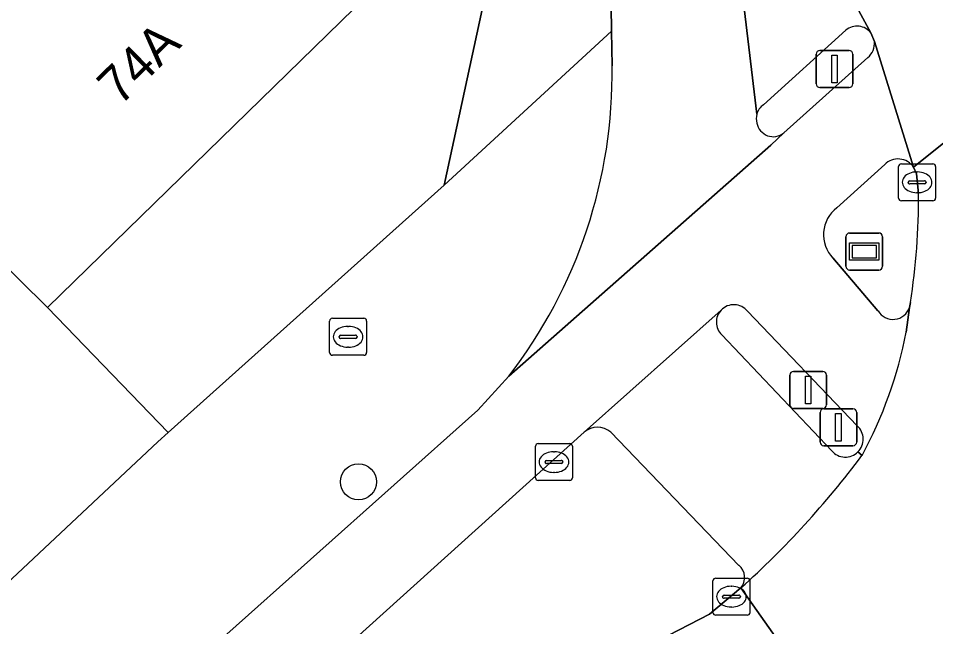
# Model space of a CAD drawing. Extents: x 161881 to 162523, y 381678 to 382381.
# Drawn here: x 162473.96 to 162498.77, y 381812.72 to 381829.16 of the extents above; entities that cross this region are included whole.
import ezdxf

# ---------------------------------------------------------------- set-up
doc = ezdxf.new("R2010")
doc.units = 0
for name, color, linetype in [('IMGEO_Boom', 7, 'Continuous'), ('IMGEO_Brandkraan', 7, 'Continuous'), ('IMGEO_Erf', 7, 'Continuous'), ('IMGEO_Fietspad_gesloten', 7, 'Continuous'), ('IMGEO_Kolk', 7, 'Continuous'), ('IMGEO_Pand', 7, 'Continuous'), ('IMGEO_Pand_nummerreeks', 7, 'Continuous'), ('IMGEO_Rijbaan_lokaal_gesloten', 7, 'Continuous'), ('IMGEO_Rijbaan_regionaal_gesloten', 7, 'Continuous'), ('IMGEO_Verkeerseiland_open', 7, 'Continuous'), ('IMGEO_Verkeersregelinstallatiepaal', 7, 'Continuous'), ('IMGEO_Voetpad_open', 7, 'Continuous'), ('IMGEO_Wegwijzer', 7, 'Continuous')]:
    doc.layers.add(name, color=color, linetype=linetype)

msp = doc.modelspace()

# ---------------------------------------------------------------- linework, layer by layer
at = {"layer": 'IMGEO_Boom'}
msp.add_circle((162483.161, 381816.631), 0.489, dxfattribs=at)
at = {"layer": 'IMGEO_Brandkraan'}
for p, q in [((162482.381, 381820.127), (162482.381, 381820.979)), ((162482.456, 381821.053), (162483.308, 381821.053)), ((162483.382, 381820.979), (162483.382, 381820.127)), ((162482.683, 381820.596), (162483.081, 381820.596)), ((162482.869, 381820.833), (162482.894, 381820.833)), ((162482.64, 381820.547), (162482.64, 381820.559)), ((162483.078, 381820.51), (162482.68, 381820.51)), ((162483.124, 381820.559), (162483.124, 381820.547)), ((162482.892, 381820.273), (162482.867, 381820.273)), ((162483.308, 381820.053), (162482.456, 381820.053))]:
    msp.add_line(p, q, dxfattribs=at)
for points in [[(162482.381, 381820.127), (162482.381, 381820.979)], [(162482.456, 381821.053), (162483.308, 381821.053)], [(162483.382, 381820.979), (162483.382, 381820.127)], [(162483.308, 381820.053), (162482.456, 381820.053)]]:
    msp.add_lwpolyline(points, dxfattribs=at)
for centre, radius, start, end in [((162482.458, 381820.977), 0.0765, 91.552, 178.448), ((162482.458, 381820.977), 0.0765, 91.552, 178.448), ((162483.306, 381820.977), 0.0765, 1.552, 88.448), ((162483.306, 381820.977), 0.0765, 1.552, 88.448), ((162482.68, 381820.556), 0.0403, 85.8775, 175.7526), ((162483.085, 381820.558), 0.0386, 1.7309, 96.639), ((162482.677, 381820.546), 0.0366, 178.938, 274.7102), ((162483.081, 381820.553), 0.043, 264.8664, 352.4533), ((162482.458, 381820.129), 0.0765, 181.552, 268.448), ((162482.458, 381820.129), 0.0765, 181.552, 268.448), ((162483.306, 381820.129), 0.0765, 271.552, 358.448), ((162483.306, 381820.129), 0.0765, 271.552, 358.448)]:
    msp.add_arc(centre, radius, start, end, dxfattribs=at)
for centre, major_axis, ratio, start_param, end_param in [((162482.868, 381820.553), (-0.387, 0.002), 0.722429, 4.712389, 7.853982), ((162482.893, 381820.553), (-0.39, 0.002), 0.717154, 1.570796, 4.712389)]:
    msp.add_ellipse(centre, major_axis=major_axis, ratio=ratio, start_param=start_param, end_param=end_param, dxfattribs=at)
at = {"layer": 'IMGEO_Erf'}
msp.add_lwpolyline([(162462.828, 381803.734), (162477.732, 381817.717), (162478.012, 381817.966), (162474.756, 381821.342), (162473.995, 381822.096), (162473.56, 381822.527)], dxfattribs=at)
at = {"layer": 'IMGEO_Fietspad_gesloten'}
for points in [[(162489.918, 381834.902), (162490.005, 381828.82), (162490.018, 381827.882)], [(162493.934, 381826.575), (162493.476, 381830.429)], [(162498.173, 381825.138), (162497.115, 381828.537)], [(162496.933, 381828.101), (162494.66, 381826.067), (162494.314, 381825.738), (162487.223, 381819.486), (162486.388, 381818.566), (162472.804, 381806.46), (162471.599, 381805.42)], [(162487.223, 381819.486), (162494.314, 381825.738), (162494.66, 381826.067)], [(162496.097, 381824.037), (162497.393, 381825.209)], [(162497.209, 381821.253), (162495.986, 381822.684)], [(162497.97, 381820.679), (162498.062, 381821.347)], [(162474.799, 381804.92), (162489.267, 381817.973), (162492.968, 381821.276)], [(162493.678, 381821.244), (162496.648, 381818.145)], [(162496.668, 381817.44), (162496.777, 381817.342)]]:
    msp.add_lwpolyline(points, dxfattribs=at)
for centre, radius, start, end in [((162496.594, 381828.498), 0.522, 310.4585, 4.2271), ((162476.678, 381827.66), 13.342, 322.2203, 0.9549), ((162494.357, 381826.457), 0.439, 164.4796, 196.4674), ((162494.376, 381826.411), 0.447, 190.0967, 309.5563), ((162497.754, 381824.859), 0.503, 33.6837, 135.9142), ((162496.641, 381823.311), 0.907, 126.8494, 223.7705), ((162493.309, 381820.949), 0.472, 38.6319, 136.2069), ((162497.614, 381821.498), 0.473, 211.2431, 341.3341), ((162486.621, 381822.855), 11.556, 331.5076, 349.1477), ((162496.328, 381817.783), 0.483, 314.6979, 48.552)]:
    msp.add_arc(centre, radius, start, end, dxfattribs=at)
at = {"layer": 'IMGEO_Kolk'}
for p, q in [((162497.767, 381824.304), (162497.767, 381825.156)), ((162497.842, 381825.23), (162498.694, 381825.23)), ((162498.768, 381825.156), (162498.768, 381824.304)), ((162498.255, 381825.01), (162498.28, 381825.01)), ((162498.026, 381824.724), (162498.026, 381824.736)), ((162498.464, 381824.687), (162498.066, 381824.687)), ((162498.069, 381824.773), (162498.467, 381824.773)), ((162498.51, 381824.736), (162498.51, 381824.724)), ((162498.278, 381824.45), (162498.253, 381824.45)), ((162498.694, 381824.23), (162497.842, 381824.23)), ((162488.022, 381817.667), (162488.874, 381817.667)), ((162487.947, 381816.741), (162487.947, 381817.593)), ((162488.435, 381817.447), (162488.46, 381817.447)), ((162488.948, 381817.593), (162488.948, 381816.741)), ((162488.206, 381817.161), (162488.206, 381817.173)), ((162488.644, 381817.124), (162488.246, 381817.124)), ((162488.249, 381817.21), (162488.647, 381817.21)), ((162488.69, 381817.173), (162488.69, 381817.161)), ((162488.458, 381816.887), (162488.433, 381816.887)), ((162488.874, 381816.667), (162488.022, 381816.667)), ((162492.747, 381813.101), (162492.747, 381813.953)), ((162492.822, 381814.027), (162493.674, 381814.027)), ((162493.748, 381813.953), (162493.748, 381813.101)), ((162493.235, 381813.807), (162493.26, 381813.807)), ((162493.006, 381813.521), (162493.006, 381813.533)), ((162493.444, 381813.484), (162493.046, 381813.484)), ((162493.049, 381813.57), (162493.447, 381813.57)), ((162493.49, 381813.533), (162493.49, 381813.521)), ((162493.258, 381813.247), (162493.233, 381813.247)), ((162493.674, 381813.027), (162492.822, 381813.027))]:
    msp.add_line(p, q, dxfattribs=at)
for points in [[(162497.767, 381824.304), (162497.767, 381825.156)], [(162497.842, 381825.23), (162498.694, 381825.23)], [(162498.768, 381825.156), (162498.768, 381824.304)], [(162498.694, 381824.23), (162497.842, 381824.23)], [(162488.022, 381817.667), (162488.874, 381817.667)], [(162487.947, 381816.741), (162487.947, 381817.593)], [(162488.948, 381817.593), (162488.948, 381816.741)], [(162488.874, 381816.667), (162488.022, 381816.667)], [(162492.747, 381813.101), (162492.747, 381813.953)], [(162492.822, 381814.027), (162493.674, 381814.027)], [(162493.748, 381813.953), (162493.748, 381813.101)], [(162493.674, 381813.027), (162492.822, 381813.027)]]:
    msp.add_lwpolyline(points, dxfattribs=at)
for centre, radius, start, end in [((162497.844, 381825.154), 0.0765, 91.552, 178.448), ((162497.844, 381825.154), 0.0765, 91.552, 178.448), ((162498.692, 381825.154), 0.0765, 1.552, 88.448), ((162498.692, 381825.154), 0.0765, 1.552, 88.448), ((162498.066, 381824.733), 0.0403, 85.8775, 175.7526), ((162498.063, 381824.723), 0.0366, 178.938, 274.7102), ((162498.467, 381824.73), 0.043, 264.8664, 352.4533), ((162498.471, 381824.735), 0.0386, 1.7309, 96.639), ((162497.844, 381824.306), 0.0765, 181.552, 268.448), ((162497.844, 381824.306), 0.0765, 181.552, 268.448), ((162498.692, 381824.306), 0.0765, 271.552, 358.448), ((162498.692, 381824.306), 0.0765, 271.552, 358.448), ((162488.024, 381817.591), 0.0765, 91.552, 178.448), ((162488.024, 381817.591), 0.0765, 91.552, 178.448), ((162488.872, 381817.591), 0.0765, 1.552, 88.448), ((162488.872, 381817.591), 0.0765, 1.552, 88.448), ((162488.246, 381817.17), 0.0403, 85.8775, 175.7526), ((162488.243, 381817.16), 0.0366, 178.938, 274.7102), ((162488.647, 381817.167), 0.043, 264.8664, 352.4533), ((162488.651, 381817.172), 0.0386, 1.7309, 96.639), ((162488.024, 381816.743), 0.0765, 181.552, 268.448), ((162488.024, 381816.743), 0.0765, 181.552, 268.448), ((162488.872, 381816.743), 0.0765, 271.552, 358.448), ((162488.872, 381816.743), 0.0765, 271.552, 358.448), ((162492.824, 381813.951), 0.0765, 91.552, 178.448), ((162492.824, 381813.951), 0.0765, 91.552, 178.448), ((162493.672, 381813.951), 0.0765, 1.552, 88.448), ((162493.672, 381813.951), 0.0765, 1.552, 88.448), ((162493.046, 381813.53), 0.0403, 85.8775, 175.7526), ((162493.043, 381813.52), 0.0366, 178.938, 274.7102), ((162493.447, 381813.527), 0.043, 264.8664, 352.4533), ((162493.451, 381813.532), 0.0386, 1.7309, 96.639), ((162492.824, 381813.103), 0.0765, 181.552, 268.448), ((162492.824, 381813.103), 0.0765, 181.552, 268.448), ((162493.672, 381813.103), 0.0765, 271.552, 358.448), ((162493.672, 381813.103), 0.0765, 271.552, 358.448)]:
    msp.add_arc(centre, radius, start, end, dxfattribs=at)
for centre, major_axis, ratio, start_param, end_param in [((162498.254, 381824.73), (-0.387, 0.002), 0.722429, 4.712389, 7.853982), ((162498.279, 381824.73), (-0.39, 0.002), 0.717154, 1.570796, 4.712389), ((162488.434, 381817.167), (-0.387, 0.002), 0.722429, 4.712389, 7.853982), ((162488.459, 381817.167), (-0.39, 0.002), 0.717154, 1.570796, 4.712389), ((162493.234, 381813.527), (-0.387, 0.002), 0.722429, 4.712389, 7.853982), ((162493.259, 381813.527), (-0.39, 0.002), 0.717154, 1.570796, 4.712389)]:
    msp.add_ellipse(centre, major_axis=major_axis, ratio=ratio, start_param=start_param, end_param=end_param, dxfattribs=at)
at = {"layer": 'IMGEO_Pand'}
msp.add_lwpolyline([(162483.099, 381832.64), (162483.484, 381833.016), (162483.846, 381832.652), (162484.047, 381832.876), (162484.135, 381832.974), (162484.06, 381833.051), (162474.369, 381842.947), (162472.454, 381844.902), (162468.874, 381841.412), (162461.809, 381834.525), (162466.185, 381830.057), (162473.56, 381822.527), (162473.995, 381822.096), (162474.756, 381821.342), (162484.123, 381830.492), (162483.825, 381830.795), (162483.431, 381830.459), (162483.054, 381830.84)], close=True, dxfattribs=at)
at = {"layer": 'IMGEO_Rijbaan_lokaal_gesloten'}
msp.add_lwpolyline([(162493.666, 381834.785), (162493.977, 381834.488), (162495.455, 381831.637), (162497.02, 381828.768), (162497.115, 381828.537), (162498.173, 381825.138), (162504.902, 381830.536), (162501.988, 381832.909), (162501.903, 381832.979), (162499.003, 381835.369), (162495.871, 381837.94)], dxfattribs=at)
at = {"layer": 'IMGEO_Rijbaan_regionaal_gesloten'}
for points in [[(162505.712, 381829.838), (162504.902, 381830.536), (162498.173, 381825.138), (162498.247, 381824.963), (162498.305, 381824.432)], [(162498.086, 381821.478), (162498.062, 381821.347), (162497.97, 381820.679)], [(162493.502, 381813.763), (162495.338, 381811.162), (162497.319, 381808.357), (162497.674, 381808.674), (162497.893, 381808.88), (162501.671, 381812.279), (162501.838, 381812.456), (162505.471, 381815.706), (162507.485, 381817.551), (162507.563, 381817.617)], [(162495.338, 381811.162), (162493.502, 381813.763), (162492.65, 381813.056), (162475.289, 381804.09)]]:
    msp.add_lwpolyline(points, dxfattribs=at)
for centre, radius, start, end in [((162479.884, 381824.313), 18.422, 351.1486, 0.3714), ((162486.621, 381822.855), 11.556, 331.5076, 349.1477), ((162476.929, 381832.216), 24.802, 311.9272, 323.152)]:
    msp.add_arc(centre, radius, start, end, dxfattribs=at)
at = {"layer": 'IMGEO_Verkeerseiland_open'}
for points in [[(162496.341, 381828.845), (162494.111, 381826.826)], [(162497.115, 381828.537), (162497.02, 381828.768)], [(162494.66, 381826.067), (162496.933, 381828.101)], [(162497.393, 381825.209), (162496.097, 381824.037)], [(162498.305, 381824.432), (162498.247, 381824.963), (162498.173, 381825.138)], [(162495.986, 381822.684), (162497.209, 381821.253)], [(162498.062, 381821.347), (162498.086, 381821.478)], [(162496.648, 381818.145), (162493.678, 381821.244)], [(162492.986, 381820.608), (162495.959, 381817.47)], [(162489.267, 381817.973), (162474.799, 381804.92)], [(162493.449, 381814.374), (162489.981, 381817.975)], [(162475.289, 381804.09), (162492.65, 381813.056), (162493.502, 381813.763)]]:
    msp.add_lwpolyline(points, dxfattribs=at)
for centre, radius, start, end in [((162496.643, 381828.477), 0.476, 37.6972, 129.3631), ((162496.594, 381828.498), 0.522, 310.4585, 4.2271), ((162494.364, 381826.46), 0.445, 124.6336, 164.985), ((162494.357, 381826.457), 0.439, 164.4796, 196.4674), ((162494.376, 381826.411), 0.447, 190.0967, 309.5563), ((162497.754, 381824.859), 0.503, 33.6837, 135.9142), ((162479.884, 381824.313), 18.422, 351.1486, 0.3714), ((162496.641, 381823.311), 0.907, 126.8494, 223.7705), ((162493.309, 381820.949), 0.472, 38.6319, 136.2069), ((162497.614, 381821.498), 0.473, 211.2431, 341.3341), ((162493.309, 381820.951), 0.471, 136.3505, 226.7365), ((162489.625, 381817.561), 0.546, 49.2951, 131.0259), ((162496.328, 381817.783), 0.483, 314.6979, 48.552), ((162496.327, 381817.783), 0.483, 220.3444, 314.8097), ((162493.17, 381814.042), 0.434, 319.9841, 49.9311)]:
    msp.add_arc(centre, radius, start, end, dxfattribs=at)
at = {"layer": 'IMGEO_Verkeersregelinstallatiepaal'}
for p, q in [((162495.637, 381828.296), (162496.427, 381828.296)), ((162496.427, 381828.296), (162495.637, 381828.296)), ((162495.537, 381827.396), (162495.537, 381828.196)), ((162495.537, 381828.196), (162495.537, 381827.396)), ((162496.527, 381828.196), (162496.527, 381827.396)), ((162496.527, 381827.396), (162496.527, 381828.196)), ((162496.427, 381827.296), (162495.637, 381827.296)), ((162495.637, 381827.296), (162496.427, 381827.296)), ((162494.927, 381819.618), (162495.717, 381819.618)), ((162495.717, 381819.618), (162494.927, 381819.618)), ((162494.827, 381818.718), (162494.827, 381819.518)), ((162494.827, 381819.518), (162494.827, 381818.718)), ((162495.817, 381819.518), (162495.817, 381818.718)), ((162495.817, 381818.718), (162495.817, 381819.518)), ((162495.717, 381818.618), (162494.927, 381818.618)), ((162494.927, 381818.618), (162495.717, 381818.618)), ((162495.743, 381818.608), (162496.533, 381818.608)), ((162496.533, 381818.608), (162495.743, 381818.608)), ((162495.643, 381817.708), (162495.643, 381818.508)), ((162495.643, 381818.508), (162495.643, 381817.708)), ((162496.633, 381818.508), (162496.633, 381817.708)), ((162496.633, 381817.708), (162496.633, 381818.508)), ((162496.533, 381817.608), (162495.743, 381817.608)), ((162495.743, 381817.608), (162496.533, 381817.608))]:
    msp.add_line(p, q, dxfattribs=at)
for points in [[(162495.957, 381828.171), (162496.107, 381828.171), (162496.107, 381827.421), (162495.957, 381827.421), (162495.957, 381828.171)], [(162495.247, 381819.493), (162495.397, 381819.493), (162495.397, 381818.743), (162495.247, 381818.743), (162495.247, 381819.493)], [(162496.063, 381818.483), (162496.213, 381818.483), (162496.213, 381817.733), (162496.063, 381817.733), (162496.063, 381818.483)]]:
    msp.add_lwpolyline(points, dxfattribs=at)
for centre, start, end in [((162495.637, 381828.196), 90, 180), ((162495.637, 381828.196), 90, 180), ((162496.427, 381828.196), 0, 90), ((162496.427, 381828.196), 360, 90), ((162495.637, 381827.396), 180, 270), ((162495.637, 381827.396), 180, 270), ((162496.427, 381827.396), 270, 0), ((162496.427, 381827.396), 270, 0), ((162494.927, 381819.518), 90, 180), ((162494.927, 381819.518), 90, 180), ((162495.717, 381819.518), 0, 90), ((162495.717, 381819.518), 360, 90), ((162494.927, 381818.718), 180, 270), ((162494.927, 381818.718), 180, 270), ((162495.743, 381818.508), 90, 180), ((162495.743, 381818.508), 90, 180), ((162495.717, 381818.718), 270, 0), ((162495.717, 381818.718), 270, 0), ((162496.533, 381818.508), 0, 90), ((162496.533, 381818.508), 360, 90), ((162495.743, 381817.708), 180, 270), ((162495.743, 381817.708), 180, 270), ((162496.533, 381817.708), 270, 0), ((162496.533, 381817.708), 270, 0)]:
    msp.add_arc(centre, 0.1, start, end, dxfattribs=at)
at = {"layer": 'IMGEO_Voetpad_open'}
for points in [[(162441.399, 381877.367), (162445.243, 381874.161), (162445.952, 381873.569), (162451.124, 381869.144), (162466.37, 381856.1), (162467.568, 381855.092), (162470.986, 381852.206), (162481.416, 381843.4), (162482.294, 381842.465), (162487.818, 381836.577), (162488.009, 381836.373), (162485.481, 381824.651), (162490.005, 381828.82), (162489.918, 381834.902)], [(162497.02, 381828.768), (162495.455, 381831.637)], [(162493.476, 381830.429), (162493.934, 381826.575)], [(162490.018, 381827.882), (162490.005, 381828.82), (162485.481, 381824.651), (162478.012, 381817.966), (162477.732, 381817.717), (162462.828, 381803.734), (162439.634, 381784.212), (162437.038, 381782.026), (162398.308, 381750), (162365.839, 381723.151), (162356.915, 381719.329), (162343.866, 381713.286), (162342.256, 381716.825), (162335.301, 381713.346), (162336.199, 381710.351)], [(162494.111, 381826.826), (162496.341, 381828.845)], [(162492.968, 381821.276), (162489.267, 381817.973)], [(162495.959, 381817.47), (162492.986, 381820.608)], [(162471.599, 381805.42), (162472.804, 381806.46), (162486.388, 381818.566), (162487.223, 381819.486)], [(162489.981, 381817.975), (162493.449, 381814.374)], [(162496.777, 381817.342), (162496.668, 381817.44)]]:
    msp.add_lwpolyline(points, dxfattribs=at)
msp.add_lwpolyline([(162488.009, 381836.373), (162487.818, 381836.577), (162486.175, 381835.035), (162480.595, 381840.829), (162479.875, 381840.136), (162475.809, 381844.357), (162474.369, 381842.947), (162484.06, 381833.051), (162484.135, 381832.974), (162484.047, 381832.876), (162485.164, 381831.701), (162484.123, 381830.492), (162474.756, 381821.342), (162478.012, 381817.966), (162485.481, 381824.651)], close=True, dxfattribs=at)
for centre, radius, start, end in [((162496.643, 381828.477), 0.476, 37.6972, 129.3631), ((162476.678, 381827.66), 13.342, 322.2203, 0.9549), ((162494.364, 381826.46), 0.445, 124.6336, 164.985), ((162493.309, 381820.951), 0.471, 136.3505, 226.7365), ((162489.625, 381817.561), 0.546, 49.2951, 131.0259), ((162496.327, 381817.783), 0.483, 220.3444, 314.8097), ((162476.929, 381832.216), 24.802, 311.9272, 323.152), ((162493.17, 381814.042), 0.434, 319.9841, 49.9311)]:
    msp.add_arc(centre, radius, start, end, dxfattribs=at)
at = {"layer": 'IMGEO_Wegwijzer'}
for p, q in [((162496.442, 381823.359), (162497.232, 381823.359)), ((162497.232, 381823.359), (162496.442, 381823.359)), ((162496.342, 381822.459), (162496.342, 381823.259)), ((162496.342, 381823.259), (162496.342, 381822.459)), ((162497.332, 381823.259), (162497.332, 381822.459)), ((162497.332, 381822.459), (162497.332, 381823.259)), ((162497.232, 381822.359), (162496.442, 381822.359)), ((162496.442, 381822.359), (162497.232, 381822.359))]:
    msp.add_line(p, q, dxfattribs=at)
for points in [[(162496.443, 381823.091), (162497.231, 381823.091), (162497.231, 381822.627), (162496.443, 381822.627), (162496.443, 381823.091)], [(162496.508, 381823.026), (162496.508, 381822.692), (162497.166, 381822.692), (162497.166, 381823.026), (162496.508, 381823.026)]]:
    msp.add_lwpolyline(points, dxfattribs=at)
for centre, start, end in [((162496.442, 381823.259), 90, 180), ((162496.442, 381823.259), 90, 180), ((162497.232, 381823.259), 0, 90), ((162497.232, 381823.259), 360, 90), ((162496.442, 381822.459), 180, 270), ((162496.442, 381822.459), 180, 270), ((162497.232, 381822.459), 270, 0), ((162497.232, 381822.459), 270, 0)]:
    msp.add_arc(centre, 0.1, start, end, dxfattribs=at)

# ---------------------------------------------------------------- texts
at = {"layer": 'IMGEO_Pand_nummerreeks'}
msp.add_text('74A', height=1, rotation=44.3297, dxfattribs=at).set_placement((162476.709, 381826.772))

doc.saveas('drawing.dxf')
